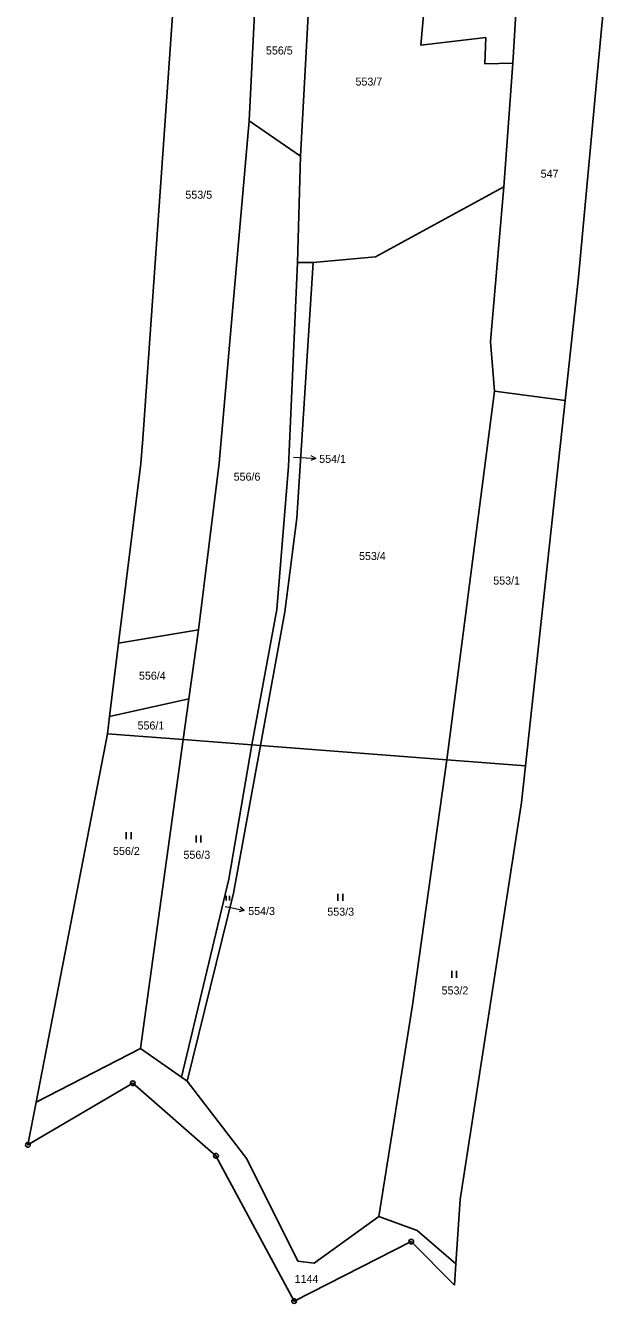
# Model space of a CAD drawing. Extents: x -765428 to -762163, y -1107632 to -1104975.
# Drawn here: x -765183.1 to -765059.2, y -1106107.9 to -1105836.4 of the extents above; entities that cross this region are included whole.
import ezdxf
from ezdxf.enums import TextEntityAlignment as Align

# ---------------------------------------------------------------- set-up
doc = ezdxf.new("R2010")
doc.units = 0
doc.header["$LTSCALE"] = 0.68
for name, color, linetype, lineweight in [('1', 7, 'Continuous', 25), ('3', 7, 'Continuous', 25), ('7', 7, 'Continuous', 13), ('8', 7, 'Continuous', 25)]:
    doc.layers.add(name, color=color, linetype=linetype, lineweight=lineweight)
doc.layers.add('2', color=7, linetype='Continuous')

msp = doc.modelspace()

# ---------------------------------------------------------------- linework, layer by layer
at = {"layer": '1'}
for p, q in [((-765099.07, -1105840.6), (-765095.63, -1105801.09)), ((-765124.66, -1105864.2), (-765121.63, -1105808.64)), ((-765079.49, -1105844.45), (-765078.16, -1105820.52)), ((-765061.76, -1105848.49), (-765059.2, -1105820.9)), ((-765158.19, -1105924.2), (-765151.31, -1105826.93)), ((-765135.57, -1105856.71), (-765134.43, -1105833.9)), ((-765085.28, -1105838.98), (-765099.07, -1105840.6)), ((-765085.46, -1105844.59), (-765085.28, -1105838.98)), ((-765079.49, -1105844.45), (-765085.46, -1105844.59)), ((-765081.46, -1105870.72), (-765079.49, -1105844.45)), ((-765065.59, -1105889.86), (-765061.76, -1105848.49)), ((-765135.57, -1105856.71), (-765141.97, -1105929.39)), ((-765135.57, -1105856.71), (-765124.66, -1105864.2)), ((-765125.27, -1105886.8), (-765124.66, -1105864.2)), ((-765108.75, -1105885.58), (-765081.46, -1105870.72)), ((-765084.29, -1105903.54), (-765081.46, -1105870.72)), ((-765127.19, -1105930.11), (-765125.27, -1105886.8)), ((-765121.97, -1105886.79), (-765125.46, -1105941.08)), ((-765125.27, -1105886.8), (-765121.97, -1105886.79)), ((-765121.97, -1105886.79), (-765108.75, -1105885.58)), ((-765068.42, -1105916.05), (-765065.59, -1105889.86)), ((-765084.29, -1105903.54), (-765083.42, -1105914.09)), ((-765093.53, -1105992.41), (-765083.42, -1105914.09)), ((-765083.42, -1105914.09), (-765068.42, -1105916.05)), ((-765076.81, -1105993.69), (-765068.42, -1105916.05)), ((-765158.56, -1105929.44), (-765158.19, -1105924.2)), ((-765163.35, -1105967.64), (-765158.56, -1105929.44)), ((-765141.97, -1105929.39), (-765146.31, -1105964.82)), ((-765129.7, -1105960.5), (-765127.19, -1105930.11)), ((-765125.46, -1105941.08), (-765127.99, -1105960.97)), ((-765135.03, -1105989.19), (-765129.7, -1105960.5)), ((-765127.99, -1105960.97), (-765133.15, -1105989.39)), ((-765146.31, -1105964.82), (-765163.35, -1105967.64)), ((-765146.31, -1105964.82), (-765148.4, -1105979.45)), ((-765165.25, -1105983.24), (-765163.35, -1105967.64)), ((-765148.4, -1105979.45), (-765165.25, -1105983.24)), ((-765148.4, -1105979.45), (-765149.57, -1105988.1)), ((-765165.7, -1105986.89), (-765165.25, -1105983.24)), ((-765180.84, -1106065.11), (-765165.7, -1105986.89)), ((-765165.7, -1105986.89), (-765149.57, -1105988.1)), ((-765149.57, -1105988.1), (-765158.69, -1106053.76)), ((-765149.57, -1105988.1), (-765135.03, -1105989.19)), ((-765139.89, -1106017.79), (-765135.03, -1105989.19)), ((-765133.15, -1105989.39), (-765138.9, -1106020.74)), ((-765135.03, -1105989.19), (-765133.15, -1105989.39)), ((-765133.15, -1105989.39), (-765093.53, -1105992.41)), ((-765100.82, -1106044.51), (-765093.53, -1105992.41)), ((-765093.53, -1105992.41), (-765076.81, -1105993.69)), ((-765077.65, -1106001.47), (-765076.81, -1105993.69)), ((-765090.72, -1106085.78), (-765077.65, -1106001.47)), ((-765149.93, -1106059.84), (-765139.89, -1106017.79)), ((-765138.9, -1106020.74), (-765148.72, -1106060.68)), ((-765108.02, -1106089.44), (-765100.82, -1106044.51)), ((-765180.84, -1106065.11), (-765158.69, -1106053.76)), ((-765158.69, -1106053.76), (-765149.93, -1106059.84)), ((-765149.93, -1106059.84), (-765148.72, -1106060.68)), ((-765182.6, -1106074.21), (-765160.3, -1106061.12)), ((-765160.3, -1106061.12), (-765142.62, -1106076.5)), ((-765148.72, -1106060.68), (-765136.03, -1106077.16)), ((-765182.6, -1106074.21), (-765180.84, -1106065.11)), ((-765142.62, -1106076.5), (-765126.01, -1106107.38)), ((-765136.03, -1106077.16), (-765125.25, -1106098.88)), ((-765091.64, -1106099.44), (-765090.72, -1106085.78)), ((-765121.75, -1106099.33), (-765108.02, -1106089.44)), ((-765126.01, -1106107.38), (-765101.11, -1106094.74)), ((-765101.11, -1106094.74), (-765091.94, -1106103.97)), ((-765125.25, -1106098.88), (-765121.75, -1106099.33)), ((-765091.94, -1106103.97), (-765091.64, -1106099.44))]:
    msp.add_line(p, q, dxfattribs=at)
msp.add_lwpolyline([(-765108.02, -1106089.44), (-765099.87, -1106092.42), (-765091.64, -1106099.44)], dxfattribs=at)
at = {"layer": '3'}
for p, q in [((-765161.681, -1106009.29), (-765161.681, -1106007.79)), ((-765160.68, -1106009.29), (-765160.68, -1106007.79)), ((-765146.861, -1106010), (-765146.861, -1106008.5)), ((-765145.86, -1106010), (-765145.86, -1106008.5)), ((-765140.432, -1106022.28), (-765140.432, -1106021.275)), ((-765139.762, -1106022.28), (-765139.762, -1106021.275)), ((-765116.691, -1106022.39), (-765116.691, -1106020.89)), ((-765115.69, -1106022.39), (-765115.69, -1106020.89)), ((-765092.521, -1106038.74), (-765092.521, -1106037.24)), ((-765091.52, -1106038.74), (-765091.52, -1106037.24))]:
    msp.add_line(p, q, dxfattribs=at)
at = {"layer": '7'}
for p, q in [((-765121.426, -1105928.419), (-765122.39, -1105927.85)), ((-765136.625, -1106024.424), (-765137.5, -1106023.726))]:
    msp.add_line(p, q, dxfattribs=at)
for points in [[(-765126.17, -1105928.09), (-765124.42, -1105928.21), (-765121.426, -1105928.419), (-765122.46, -1105928.849)], [(-765140.69, -1106023.57), (-765139.56, -1106023.8), (-765136.625, -1106024.424), (-765137.708, -1106024.706)]]:
    msp.add_lwpolyline(points, dxfattribs=at)
at = {"layer": '8'}
for centre, radius in [((-765160.3, -1106061.1199), 0.5), ((-765160.3, -1106061.1199), 0.0303), ((-765182.6, -1106074.2099), 0.5), ((-765182.6, -1106074.2099), 0.0303), ((-765142.62, -1106076.4999), 0.5), ((-765142.62, -1106076.4999), 0.0303), ((-765101.11, -1106094.7399), 0.5), ((-765101.11, -1106094.7399), 0.0303), ((-765126.01, -1106107.3799), 0.5), ((-765126.01, -1106107.3799), 0.0303)]:
    msp.add_circle(centre, radius, dxfattribs=at)

# ---------------------------------------------------------------- texts
at = {"layer": '2'}
for s, p in [('556/5', (-765129.16, -1105842.585)), ('553/7', (-765110.12, -1105849.195)), ('547', (-765071.709, -1105868.765)), ('553/5', (-765146.28, -1105873.225)), ('556/6', (-765136.02, -1105933.105)), ('553/4', (-765109.37, -1105949.965)), ('553/1', (-765080.85, -1105955.185)), ('556/4', (-765156.15, -1105975.385)), ('556/1', (-765156.45, -1105985.965)), ('556/2', (-765161.66, -1106012.615)), ('556/3', (-765146.69, -1106013.425)), ('553/3', (-765116.11, -1106025.515)), ('553/2', (-765091.82, -1106042.245))]:
    msp.add_text(s, height=1.7, dxfattribs=at).set_placement(p, align=Align.CENTER)
for s, p in [('554/1', (-765120.68, -1105929.335)), ('554/3', (-765135.78, -1106025.375)), ('1144', (-765125.91, -1106103.525))]:
    msp.add_text(s, height=1.7, dxfattribs=at).set_placement(p)

doc.saveas('drawing.dxf')
